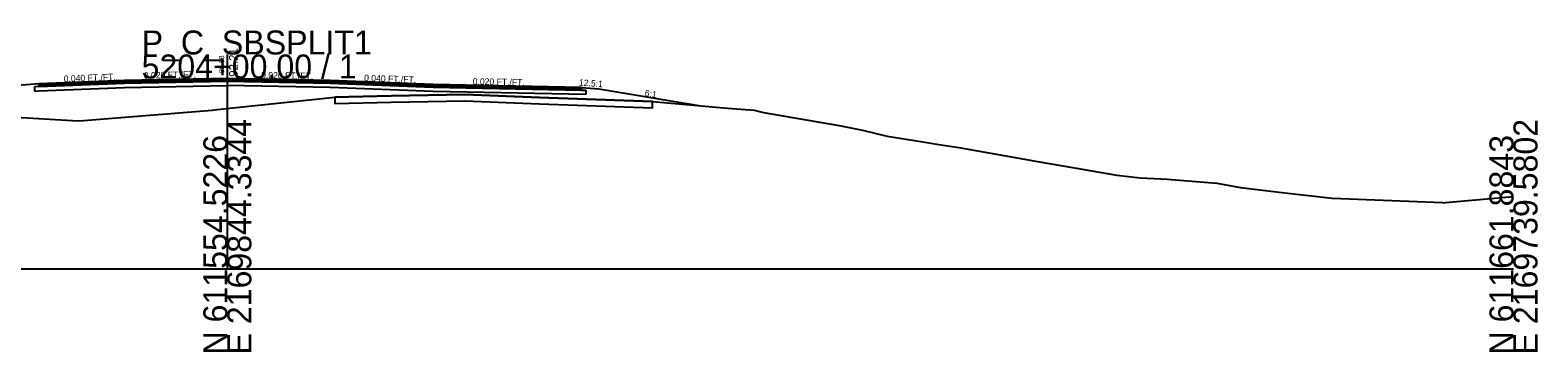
# Model space of a CAD drawing. Extents: x -26 to 1303, y -3010 to 12023.
# Drawn here: x 1127 to 1302.8, y 3990.3 to 4027.8 of the extents above; entities that cross this region are included whole.
import ezdxf

# ---------------------------------------------------------------- set-up
doc = ezdxf.new("R2010")
doc.units = 0
for name, color, linetype in [('RD_GPK_XS_Cell', 7, 'Continuous'), ('RD_XS_Base', 7, 'Continuous'), ('RD_XS_ExGround', 7, 'Continuous'), ('RD_XS_ExPaveRet', 7, 'Continuous'), ('RD_XS_Greenside', 7, 'Continuous'), ('RD_XS_Pave', 7, 'Continuous'), ('RD_XS_PaveOvlay_CP', 7, 'Continuous'), ('RD_XS_TieSlope', 7, 'Continuous'), ('RD_XS_TX_Elev_EX', 7, 'Continuous'), ('RD_XS_TX_Elev_PR', 7, 'Continuous'), ('RD_XS_TX_ShdSlope', 7, 'Continuous'), ('RD_XS_TX_Slope', 7, 'Continuous')]:
    doc.layers.add(name, color=color, linetype=linetype)

msp = doc.modelspace()

# ---------------------------------------------------------------- linework, layer by layer
at = {"layer": 'RD_GPK_XS_Cell'}
for p, q in [((1150, 4000), (1150, 4025)), ((1000, 4000), (1150, 4000)), ((1150, 4000), (1300, 4000))]:
    msp.add_line(p, q, dxfattribs=at)
at = {"layer": 'RD_XS_Base'}
for p, q in [((1138, 4021.66), (1128, 4021.26)), ((1136, 4021.58), (1136, 4021.58)), ((1150, 4021.9), (1138, 4021.66)), ((1138, 4021.16), (1150, 4021.4)), ((1150, 4021.4), (1150, 4022.05)), ((1150, 4022.05), (1150, 4022.05)), ((1150, 4022.05), (1150, 4022.05)), ((1150, 4022.05), (1150, 4021.9)), ((1150, 4021.9), (1150, 4021.9)), ((1150, 4021.9), (1162, 4021.66)), ((1150, 4021.9), (1150, 4021.9)), ((1150, 4021.4), (1150, 4021.9)), ((1150, 4021.9), (1150, 4021.9)), ((1150, 4021.9), (1150, 4021.9)), ((1162, 4021.16), (1150, 4021.4)), ((1150, 4021.4), (1150, 4021.4)), ((1150, 4021.4), (1150, 4021.4)), ((1162, 4021.66), (1162, 4021.66)), ((1162, 4021.66), (1174, 4021.18)), ((1128, 4021.26), (1127.5, 4021.24)), ((1127.5, 4021.24), (1127.5, 4021.24)), ((1127.5, 4021.24), (1127.5, 4020.74)), ((1127.5, 4020.74), (1128, 4020.76)), ((1128, 4021.26), (1128, 4021.26)), ((1128, 4020.76), (1138, 4021.16)), ((1128, 4020.76), (1128, 4020.76)), ((1136, 4021.08), (1136, 4021.08)), ((1174, 4020.68), (1162, 4021.16)), ((1162, 4021.16), (1162, 4021.16)), ((1174, 4021.18), (1174, 4021.18)), ((1174, 4021.18), (1191.32, 4020.83)), ((1191.82, 4020.32), (1174, 4020.68)), ((1174, 4020.68), (1174, 4020.68)), ((1191.32, 4020.83), (1191.32, 4020.83)), ((1191.32, 4020.83), (1191.82, 4020.82)), ((1191.82, 4020.82), (1191.82, 4020.82)), ((1191.82, 4020.82), (1191.82, 4020.32))]:
    msp.add_line(p, q, dxfattribs=at)
at = {"layer": 'RD_XS_ExGround'}
msp.add_lwpolyline([(1115.38, 4018.27), (1131.96, 4017.31), (1132.77, 4017.28), (1134.18, 4017.39), (1148.22, 4018.5), (1148.82, 4018.57), (1162.52, 4020.04), (1169.09, 4020.18), (1177.69, 4020.33), (1186.41, 4020), (1199.6, 4019.51), (1208.33, 4018.75), (1211.45, 4018.51), (1212.55, 4018.25), (1221.36, 4016.71), (1224.08, 4016.16), (1226.94, 4015.47), (1230.88, 4014.84), (1232.96, 4014.5), (1235.3, 4014.16), (1242.97, 4012.78), (1244.49, 4012.5), (1248.79, 4011.77), (1253.74, 4010.94), (1256.45, 4010.6), (1258.9, 4010.5), (1259.6, 4010.47), (1265.42, 4009.98), (1268.17, 4009.47), (1273.32, 4008.86), (1278.86, 4008.24), (1291.74, 4007.72), (1291.8, 4007.71), (1292.07, 4007.74), (1300, 4008.44)], dxfattribs=at)
at = {"layer": 'RD_XS_ExPaveRet'}
for points in [[(1186.41, 4020), (1177.69, 4020.33), (1177.69, 4020.33), (1169.09, 4020.18), (1169.09, 4020.18), (1162.52, 4020.04), (1162.52, 4020.04), (1162.52, 4020.04), (1162.52, 4020.04), (1162.52, 4019.29), (1162.52, 4019.29), (1162.52, 4019.29), (1169.09, 4019.43), (1169.09, 4019.43), (1177.69, 4019.58), (1177.69, 4019.58), (1186.41, 4019.25), (1186.41, 4019.25), (1199.6, 4018.76), (1199.6, 4019.51), (1199.6, 4019.51), (1186.41, 4020), (1186.41, 4020)], [(1186.41, 4020), (1177.69, 4020.33), (1169.09, 4020.18), (1162.52, 4020.04), (1162.52, 4019.29), (1169.09, 4019.43), (1177.69, 4019.58), (1186.41, 4019.25), (1199.6, 4018.76), (1199.6, 4019.51), (1186.41, 4020)]]:
    msp.add_lwpolyline(points, dxfattribs=at)
at = {"layer": 'RD_XS_Greenside'}
msp.add_line((1193.32, 4020.99), (1204.97, 4019.05), dxfattribs=at)
at = {"layer": 'RD_XS_Pave'}
for p, q in [((1138, 4021.97), (1128, 4021.57)), ((1138, 4021.81), (1128, 4021.41)), ((1128, 4021.41), (1138, 4021.81)), ((1128, 4021.26), (1138, 4021.66)), ((1128, 4021.57), (1128, 4021.57)), ((1128, 4021.57), (1128, 4021.41)), ((1128, 4021.41), (1128, 4021.41)), ((1128, 4021.41), (1128, 4021.26)), ((1136, 4021.89), (1136, 4021.89)), ((1136, 4021.73), (1136, 4021.73)), ((1136, 4021.73), (1136, 4021.73)), ((1136, 4021.58), (1136, 4021.58)), ((1150, 4022.21), (1138, 4021.97)), ((1150, 4022.05), (1138, 4021.81)), ((1138, 4021.81), (1150, 4022.05)), ((1138, 4021.66), (1150, 4021.9)), ((1162, 4021.97), (1150, 4022.21)), ((1150, 4022.21), (1150, 4022.21)), ((1150, 4022.21), (1150, 4022.21)), ((1150, 4021.9), (1150, 4022.05)), ((1150, 4022.05), (1150, 4022.05)), ((1150, 4022.05), (1150, 4022.05)), ((1150, 4022.05), (1150, 4022.05)), ((1150, 4022.05), (1150, 4022.05)), ((1150, 4022.05), (1162, 4021.81)), ((1162, 4021.81), (1150, 4022.05)), ((1150, 4022.05), (1150, 4022.05)), ((1150, 4022.05), (1150, 4022.05)), ((1150, 4022.05), (1150, 4022.05)), ((1150, 4022.05), (1150, 4021.9)), ((1150, 4021.9), (1150, 4021.9)), ((1150, 4021.9), (1150, 4021.9)), ((1150, 4021.9), (1150, 4021.9)), ((1150, 4021.9), (1162, 4021.66)), ((1174, 4021.49), (1162, 4021.97)), ((1162, 4021.97), (1162, 4021.97)), ((1162, 4021.81), (1162, 4021.81)), ((1162, 4021.81), (1174, 4021.33)), ((1174, 4021.33), (1162, 4021.81)), ((1162, 4021.81), (1162, 4021.81)), ((1162, 4021.66), (1162, 4021.66)), ((1162, 4021.66), (1174, 4021.18)), ((1191.32, 4021.15), (1174, 4021.49)), ((1174, 4021.49), (1174, 4021.49)), ((1174, 4021.33), (1174, 4021.33)), ((1174, 4021.33), (1191.32, 4020.99)), ((1191.32, 4020.99), (1174, 4021.33)), ((1174, 4021.33), (1174, 4021.33)), ((1174, 4021.18), (1191.32, 4020.83)), ((1174, 4021.18), (1174, 4021.18)), ((1191.32, 4020.99), (1191.32, 4021.15)), ((1191.32, 4021.15), (1191.32, 4021.15)), ((1191.32, 4020.83), (1191.32, 4020.99)), ((1191.32, 4020.99), (1191.32, 4020.99))]:
    msp.add_line(p, q, dxfattribs=at)
at = {"layer": 'RD_XS_PaveOvlay_CP'}
for p, q in [((1138, 4021.97), (1128, 4021.57)), ((1136, 4021.89), (1136, 4021.89)), ((1150, 4022.21), (1138, 4021.97)), ((1162, 4021.97), (1150, 4022.21)), ((1150, 4022.21), (1150, 4022.21)), ((1150, 4022.21), (1150, 4022.21)), ((1174, 4021.49), (1162, 4021.97)), ((1162, 4021.97), (1162, 4021.97)), ((1191.32, 4021.15), (1174, 4021.49)), ((1174, 4021.49), (1174, 4021.49))]:
    msp.add_line(p, q, dxfattribs=at)
at = {"layer": 'RD_XS_TieSlope'}
for p, q in [((1128, 4021.57), (1122, 4021.09)), ((1191.32, 4021.15), (1193.32, 4020.99))]:
    msp.add_line(p, q, dxfattribs=at)

# ---------------------------------------------------------------- texts
at = {"layer": 'RD_GPK_XS_Cell'}
for s, p in [('P_C_SBSPLIT1', (1140, 4025)), ('5204+00.00 / 1', (1140, 4022.2))]:
    msp.add_text(s, height=2.8, dxfattribs=at).set_placement(p)
for s, p in [('E 2169844.3344', (1152.8, 3990)), ('E 2169739.5802', (1302.8, 3990)), ('N 611554.5226', (1150, 3990)), ('N 611661.8843', (1300, 3990))]:
    msp.add_text(s, height=2.8, rotation=90, dxfattribs=at).set_placement(p)
at = {"layer": 'RD_XS_TX_Elev_EX'}
msp.add_text('88.68', height=0.6, rotation=90, dxfattribs=at).set_placement((1149.63, 4022.82))
at = {"layer": 'RD_XS_TX_Elev_PR'}
msp.add_text('92.21', height=1, rotation=90, dxfattribs=at).set_placement((1151.2, 4022.4))
at = {"layer": 'RD_XS_TX_ShdSlope'}
msp.add_text('12.5:1', height=0.75, rotation=355.4261, dxfattribs=at).set_placement((1190.99, 4021.39))
at = {"layer": 'RD_XS_TX_Slope'}
for s, rotation, p in [('0.040 FT./FT.', 2.2906, (1130.93, 4021.79)), ('0.020 FT./FT.', 1.1458, (1140.27, 4022.18)), ('0.020 FT./FT.', 358.8542, (1153.94, 4022.23)), ('0.040 FT./FT.', 357.7094, (1165.94, 4021.91)), ('0.020 FT./FT.', 358.8542, (1178.61, 4021.5)), ('6:1', 350.5377, (1198.63, 4020.16))]:
    msp.add_text(s, height=0.75, rotation=rotation, dxfattribs=at).set_placement(p)

doc.saveas('drawing.dxf')
